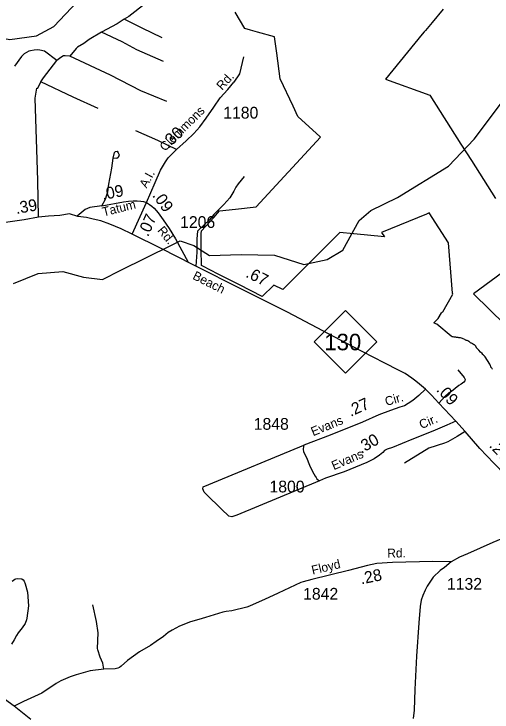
# Model space of a CAD drawing. Extents: x 2104537 to 2336408, y 34176 to 229611.
# Drawn here: x 2197655 to 2202724, y 77773 to 85176 of the extents above; entities that cross this region are included whole.
import ezdxf

# ---------------------------------------------------------------- set-up
doc = ezdxf.new("R2010")
doc.units = 0
for name, color, linetype in [('Exist Boundary Political City Limit New', 7, 'Continuous'), ('Exist Hydrographic Creek Single Shore', 7, 'Continuous'), ('Exist Road Non-System Type 51', 7, 'Continuous'), ('Exist Road Primary NC Attributed', 7, 'Continuous'), ('Exist Road Primary NC Label', 7, 'Continuous'), ('Exist Road Primary NC Mileage Hundredths English Label', 7, 'Continuous'), ('Exist Road Primary NC Shield CELL', 7, 'Continuous'), ('Exist Road Primary NC Shield Number Label', 7, 'Continuous'), ('Exist Road Secondary Mileage Hundredths English Label', 7, 'Continuous'), ('Exist Road Secondary Type 51 Attributed', 7, 'Continuous'), ('Exist Road Secondary Type 51 Label', 7, 'Continuous'), ('Exist Road Secondary Type 51 Number Label', 7, 'Continuous'), ('Map Preparation Boundary City Limit Buffer Line', 7, 'Continuous')]:
    doc.layers.add(name, color=color, linetype=linetype)

msp = doc.modelspace()

# ---------------------------------------------------------------- linework, layer by layer
at = {"layer": 'Exist Boundary Political City Limit New'}
for points in [[(2202204.2, 85228.7), (2202087.8, 85086.7)], [(2200288, 82179.3), (2200045.5, 82303.6), (2200004.8, 82324.6), (2199934.5, 82360), (2199821.2, 82417), (2199656.2, 82500), (2199643, 82506.9), (2199641, 82676.7), (2199639.2, 82845.5), (2199641.8, 82874.5), (2199772.5, 83017.8), (2199835.2, 83088.4), (2200004.8, 83106.6), (2200222, 83129.9), (2200905.8, 83869.1), (2200903.2, 83871.4), (2200666.5, 84087.6), (2200615.5, 84197), (2200479, 84489.6), (2200440.5, 84758.7), (2200416.2, 84933.5), (2200237.5, 84984.8), (2200163.8, 85005.9), (2200101.2, 85023.7), (2200000, 85193.9)], [(2202087.8, 85086.7), (2202016.8, 85000), (2202005.8, 84986.6), (2201984.8, 84961), (2201594, 84483.4), (2202064.2, 84314.4), (2202394, 83796.4), (2202504.8, 83623.1), (2202760.8, 83220)], [(2202714.5, 81427.8), (2202712.8, 81431.9), (2202710.5, 81435.9), (2202707.5, 81443.5), (2202706, 81447.4), (2202704.2, 81453), (2202703.8, 81454.5), (2202699.5, 81461.9), (2202649.8, 81538.7), (2202644.8, 81546.4), (2202642.8, 81549.4), (2202641.5, 81551), (2202638.5, 81553.9), (2202636.2, 81556.2), (2202634, 81558), (2202630.8, 81560.6), (2202628.2, 81562.5), (2202625.5, 81565.5), (2202617.5, 81574.4), (2202601.8, 81590.9), (2202582.2, 81611.7), (2202568.2, 81625.8), (2202565.8, 81627.9), (2202563.2, 81630.8), (2202561.2, 81633.2), (2202559.8, 81635.7), (2202558.2, 81638.6), (2202556.8, 81641.4), (2202554.8, 81646), (2202552.5, 81651), (2202550.8, 81654.3), (2202548.5, 81657.5), (2202546.5, 81659.6), (2202544.5, 81661.5), (2202542.8, 81662.9), (2202540.5, 81664.4), (2202538.2, 81665.8), (2202535.5, 81667.2), (2202533.8, 81668.2), (2202531.8, 81669.5), (2202530.5, 81670.3), (2202527.8, 81671.9), (2202522.2, 81675.3), (2202520.2, 81676.5), (2202517.8, 81677.9), (2202515.8, 81679.1), (2202514, 81680.1), (2202511.8, 81681.3), (2202504.8, 81684.6), (2202501, 81686.2), (2202496.2, 81689), (2202491, 81691.7), (2202483.5, 81697.6), (2202476.2, 81702.6), (2202467.5, 81708.3), (2202459, 81712.2), (2202449.2, 81714.3), (2202444.5, 81716.5), (2202439.5, 81719.3), (2202434, 81722.4), (2202417.8, 81729.9), (2202409.5, 81733.9), (2202401.2, 81737.8), (2202391.2, 81739.9), (2202382.2, 81741.1), (2202370.5, 81742.5), (2202364, 81744.4), (2202356.5, 81745.2), (2202348.2, 81746.4), (2202340, 81747.4), (2202330.5, 81748.3), (2202323.2, 81750.2), (2202313.5, 81750.9), (2202309.2, 81752), (2202302.8, 81753.8), (2202296.5, 81755.7), (2202292.2, 81757.9), (2202289.8, 81759.9), (2202137.5, 81886.4), (2202128, 81890.3), (2202105.5, 81901.6), (2202152.5, 81945.2), (2202186.8, 82006.2), (2202195, 82012), (2202202.8, 82017.7), (2202306.5, 82206.1), (2202306, 82213.7), (2202261.8, 82748.2), (2202056.5, 83066.1), (2202027.8, 83051.3), (2201550.5, 82857.1), (2201585, 82813.8), (2201258, 82845.5), (2201257.2, 82845.1), (2201253.5, 82845.5), (2201110.2, 82859.4), (2200752.8, 82500), (2200506.2, 82252.5), (2200411.8, 82301.5), (2200288, 82179.3)], [(2202902.2, 82482.8), (2202527.8, 82207.4), (2203532.2, 81224.5)], [(2202727.8, 81408.3), (2202723.8, 81412.6), (2202720, 81418.2), (2202716.5, 81424.3), (2202714.5, 81427.8)]]:
    msp.add_lwpolyline(points, dxfattribs=at)
at = {"layer": 'Exist Hydrographic Creek Single Shore'}
for points in [[(2197393.7, 84998.8), (2197476.7, 84931.5), (2197610.6, 84906), (2197893.6, 84943.1), (2198076.7, 85044.6), (2198448.7, 85437.7), (2198597.8, 85530), (2198946.8, 85631.5), (2199129.7, 85769), (2199418.8, 86084.9), (2199707.7, 86437), (2199831.8, 86638), (2200086.6, 87197.4), (2200225.7, 87450.6), (2200663.7, 88062.1), (2200770.7, 88220.8), (2200985.8, 88456.2)], [(2197651.5, 82316.3), (2197912.9, 82423.4), (2198174.3, 82444.9), (2198392.8, 82384.9), (2198594.2, 82359.1), (2198787, 82457.7), (2199326.8, 82723.6), (2199416.8, 82770.7), (2199562.5, 82719.3), (2199729.6, 82616.4), (2200063.8, 82624.9), (2200417.8, 82617.6), (2200726.8, 82519.7), (2200975.7, 82574), (2201141.8, 82672.5), (2201314.7, 82984.1), (2201438.8, 83093.2), (2201721.7, 83228.9), (2202260.8, 83562.9), (2202533.7, 83849.6), (2202962.7, 84418.8)]]:
    msp.add_lwpolyline(points, dxfattribs=at)
at = {"layer": 'Exist Road Non-System Type 51'}
for points in [[(2199254.6, 85469), (2199106.3, 85333.1), (2199051, 85288.2), (2198872.8, 85149.9), (2198823, 85121.4)], [(2198823, 85121.4), (2198749.6, 85072.3), (2198584.8, 84982.3)], [(2199227.6, 84922.6), (2199014.4, 85023.8), (2198823, 85121.4)], [(2198584.8, 84982.3), (2198453.7, 84904.4), (2198394.2, 84863.9), (2198327.5, 84823.5), (2198313.1, 84810.7), (2198245.9, 84730)], [(2199239.2, 84670.8), (2198957.2, 84796.9), (2198802.3, 84879), (2198584.8, 84982.3)], [(2198108.6, 84684.1), (2197979.2, 84780.4), (2197928.6, 84793.5), (2197901.1, 84795.4), (2197867.9, 84792.7), (2197829.1, 84786.2), (2197812.9, 84781), (2197761.5, 84753.8), (2197734, 84725.1), (2197661.2, 84622.2)], [(2198245.9, 84730), (2198199.1, 84732.5), (2198182, 84730.9), (2198152.1, 84714.7), (2198108.6, 84684.1)], [(2199274.6, 84247.2), (2199000.9, 84361.4), (2198678.7, 84527.4), (2198245.9, 84730)], [(2200087.8, 84722), (2200045.7, 84542), (2199987.3, 84451.2)], [(2197941.4, 84455.7), (2197969.2, 84498.1), (2198108.6, 84684.1)], [(2197916.4, 83019.9), (2197907.5, 83408.4), (2197881.5, 84281.6), (2197896.8, 84388.8), (2197906.4, 84390.7), (2197941.4, 84455.7)], [(2198549.2, 84173.6), (2198281.8, 84294.2), (2197941.4, 84455.7)], [(2199379.4, 83740.3), (2199182, 83834), (2198946.5, 83936.9)], [(2198706.3, 83647.6), (2198720.9, 83706.1), (2198732.6, 83717), (2198749.1, 83719.9), (2198761.5, 83704.3), (2198767.8, 83688.4), (2198769.3, 83682.2), (2198764.3, 83660.6), (2198758.3, 83652.5), (2198744.3, 83644.3), (2198706.3, 83647.6)], [(2198585, 83140.1), (2198624.1, 83210.6), (2198641.1, 83259.8), (2198648.9, 83290.8), (2198660, 83371), (2198691.8, 83539.6), (2198706.3, 83647.6)], [(2200094.9, 83453.3), (2200033.3, 83376.3), (2200006.9, 83341), (2199987.1, 83297), (2199945.3, 83226.6), (2199881.5, 83156.1), (2199822.1, 83098.9), (2199773.7, 83050.5), (2199729.7, 82993.3), (2199670.3, 82938.2), (2199602.1, 82872.2), (2199593.3, 82790.8), (2199595.5, 82649.9), (2199583.1, 82502.4)], [(2198585, 83140.1), (2198459.8, 83123.4), (2198409.8, 83102.2), (2198324.6, 83030.7)], [(2199369.5, 82790.1), (2199502, 82543.3)], [(2202362.7, 81402.9), (2202427.7, 81321.6), (2202438.1, 81299.7), (2202436.2, 81284), (2202424.4, 81269.8), (2202396.8, 81249.3), (2202372.9, 81237), (2202293.6, 81171.9), (2202265.8, 81157.7), (2202226.4, 81123), (2202161.3, 81050.1)], [(2202439.3, 80749.8), (2202355.9, 80694.7), (2202255.4, 80638.9), (2202219, 80622.8), (2202053.3, 80570.9), (2201794.6, 80411.3)], [(2200895, 80223.6), (2200018.2, 79860.9), (2199966, 79844.6), (2199934.5, 79849.4), (2199929.6, 79853.4), (2199857.4, 79920.4), (2199691.1, 80088.3), (2199672.3, 80105.8), (2199659.2, 80141.8), (2199662.5, 80161.4), (2199721.2, 80187.5), (2200728.9, 80603.7)], [(2200728.9, 80603.7), (2200723.6, 80588.1), (2200720.1, 80562.3), (2200725.1, 80534.2), (2200757.6, 80470.7), (2200788.5, 80391.9), (2200819.4, 80323.8), (2200847.3, 80274.3), (2200857.5, 80258.6), (2200866.9, 80244.5), (2200884.5, 80230.4), (2200895, 80223.6)], [(2197634.8, 79159.5), (2197665.1, 79183.5), (2197674.3, 79186), (2197695.4, 79189.2), (2197738.3, 79184.8), (2197752.8, 79173.6), (2197762.8, 79161), (2197773.4, 79133.2), (2197798.2, 79043.5), (2197808.2, 78897.6), (2197790, 78769.4), (2197786.3, 78751.4), (2197772.8, 78713.3), (2197743.1, 78667), (2197700, 78614.3), (2197682.8, 78586.4), (2197658.9, 78537.7), (2197629.5, 78493.6)], [(2200813.4, 79179.4), (2200722.4, 79154.3), (2200694.9, 79145.1), (2200455.4, 79032.9), (2200359.1, 78986.5), (2200318.1, 78970.9), (2200153, 78896.7), (2200122.9, 78885.5), (2199965.6, 78846.5), (2199903.8, 78839.5), (2199869.9, 78832.9), (2199686.4, 78776.8), (2199616.7, 78753.8), (2199525.1, 78728.7), (2199411.6, 78683), (2199334.1, 78642.1), (2199290.6, 78615.8), (2199240.9, 78575.1), (2199163.7, 78520.1), (2199102.3, 78479.3), (2198987.1, 78411.6), (2198858, 78319.6), (2198791.3, 78259.3), (2198773.3, 78247.1), (2198755.4, 78238.6), (2198727.4, 78230.3), (2198609.5, 78226.7)], [(2198609.5, 78226.7), (2198597.7, 78290.9), (2198569.7, 78356.4), (2198542.6, 78431.7), (2198540, 78447.2), (2198546.5, 78614), (2198530.7, 78733.8), (2198492.2, 78911.3)], [(2198609.5, 78226.7), (2198461.6, 78208.9), (2198315.1, 78169), (2198250.4, 78148), (2198150.8, 78103), (2198101.4, 78074.1), (2197950.1, 77974), (2197755.9, 77885.9), (2197656.5, 77836.6)]]:
    msp.add_lwpolyline(points, dxfattribs=at)
at = {"layer": 'Exist Road Primary NC Attributed'}
for points in [[(2198910, 82840.3), (2198792.8, 82897.7), (2198670.7, 82947.4), (2198575.2, 82981.8), (2198495.1, 83000.9), (2198424.4, 83016.1), (2198332.8, 83029.5), (2198244.2, 83056.3), (2198140, 83037.2), (2198021.7, 83031.4), (2197916.7, 83020), (2197764, 82993.2), (2197540.7, 82960.8), (2197359.3, 82930.2), (2197281.1, 82926.4), (2197164.3, 82918.8), (2197082.2, 82920.7), (2197015.4, 82928.3), (2196924.4, 82951.6)], [(2202017.5, 81197), (2201956.5, 81249.6), (2201917.2, 81281.6), (2201875.2, 81314.1), (2201804.5, 81361.8), (2201733.9, 81398.1), (2201588.9, 81472.6), (2201464.8, 81537.5), (2201246, 81650.6), (2200557, 82013.4), (2200089.3, 82248.3), (2199556.7, 82515.6), (2199217, 82687.5), (2198910, 82840.3)], [(2202339.4, 80858), (2202161.3, 81050.1), (2202082.3, 81135), (2202017.5, 81197)], [(2203300, 79807.4), (2203159.5, 79969.2), (2202997.4, 80139), (2202871.6, 80283.2), (2202741.9, 80413.9), (2202595.6, 80569.6), (2202439.3, 80749.8), (2202339.4, 80858)]]:
    msp.add_lwpolyline(points, dxfattribs=at)
at = {"layer": 'Exist Road Primary NC Shield CELL'}
msp.add_lwpolyline([(2200837, 81699.1), (2201170, 82032.1), (2201502.9, 81699.1), (2201170, 81366.1)], close=True, dxfattribs=at)
at = {"layer": 'Exist Road Secondary Type 51 Attributed'}
msp.add_line((2198910, 82840.3), (2199059.2, 83176.1), dxfattribs=at)
for points in [[(2199059.2, 83176.1), (2199151, 83387.9), (2199208.7, 83519.7), (2199260.2, 83608.3), (2199288.4, 83649.2), (2199329.8, 83687.7), (2199379.4, 83740.3), (2199480.2, 83831.8), (2199563, 83907.1), (2199624.8, 83979.3), (2199692.8, 84072), (2199773.1, 84187.4), (2199843.1, 84286.3), (2199921.4, 84374.9), (2199987.3, 84451.2)], [(2198585, 83140.1), (2198816.1, 83184.3), (2198868.3, 83191.2), (2198920.5, 83195.3), (2198961.7, 83195.3), (2199001.5, 83192.6), (2199027.6, 83187.1), (2199059.2, 83176.1)], [(2199059.2, 83176.1), (2199093.5, 83155.5), (2199118.2, 83137.6), (2199142.9, 83117), (2199182.8, 83068.9), (2199237.7, 82992), (2199300.9, 82900), (2199369.5, 82790.1)], [(2202017.5, 81197), (2201949.2, 81131.2), (2201883, 81078.5), (2201836.1, 81046.6), (2201794.4, 81021.9), (2201746, 81005.3), (2201646.8, 80972.2), (2201522, 80923.9), (2201350.3, 80846.2), (2201007.9, 80708.7), (2200728.9, 80603.7)], [(2202339.4, 80858), (2202243.8, 80816.4), (2202097.3, 80751), (2201873.5, 80663.8), (2201667.6, 80578.6), (2201612.1, 80560.8), (2201584.4, 80545), (2201564.6, 80525.1), (2201529, 80497.4), (2201475.5, 80457.8), (2201396.3, 80418.2), (2201156.7, 80321.1), (2200959.3, 80254.5), (2200895, 80223.6)], [(2203300, 79807.4), (2203190.6, 79761.9), (2202732.9, 79570.8), (2202463.6, 79451.9), (2202380.5, 79416.2), (2202291.8, 79366.1)], [(2202291.8, 79366.1), (2202095.4, 79368), (2201669.2, 79358.8), (2201500.9, 79346.9), (2201403.8, 79327.1), (2201201.9, 79275.6), (2200813.4, 79179.4)], [(2202291.8, 79366.1), (2202218.3, 79307.6), (2202174.6, 79275), (2202099.4, 79202), (2202034.6, 79109.1), (2202013.2, 79066.8), (2201990, 79007.9), (2201974.1, 78958.4), (2201962.2, 78891.1), (2201946.4, 78717.7), (2201924.6, 78367.1), (2201906.8, 78013.8), (2201898.9, 77793.9), (2201889, 77704.8)], [(2197834.2, 77695.2), (2197656.5, 77836.6), (2197357.8, 78052.1)]]:
    msp.add_lwpolyline(points, dxfattribs=at)
at = {"layer": 'Map Preparation Boundary City Limit Buffer Line'}
for points in [[(2202204.2, 85228.7), (2202087.8, 85086.7)], [(2200288, 82179.3), (2200045.5, 82303.6), (2200004.8, 82324.6), (2199934.5, 82360), (2199821.2, 82417), (2199656.2, 82500), (2199643, 82506.9), (2199641, 82676.7), (2199639.2, 82845.5), (2199641.8, 82874.5), (2199772.5, 83017.8), (2199835.2, 83088.4), (2200004.8, 83106.6), (2200222, 83129.9), (2200905.8, 83869.1), (2200903.2, 83871.4), (2200666.5, 84087.6), (2200615.5, 84197), (2200479, 84489.6), (2200440.5, 84758.7), (2200416.2, 84933.5), (2200237.5, 84984.8), (2200163.8, 85005.9), (2200101.2, 85023.7), (2200000, 85193.9)], [(2202087.8, 85086.7), (2202016.8, 85000), (2202005.8, 84986.6), (2201984.8, 84961), (2201594, 84483.4), (2202064.2, 84314.4), (2202394, 83796.4), (2202504.8, 83623.1), (2202760.8, 83220)], [(2202714.5, 81427.8), (2202712.8, 81431.9), (2202710.5, 81435.9), (2202707.5, 81443.5), (2202706, 81447.4), (2202704.2, 81453), (2202703.8, 81454.5), (2202699.5, 81461.9), (2202649.8, 81538.7), (2202644.8, 81546.4), (2202642.8, 81549.4), (2202641.5, 81551), (2202638.5, 81553.9), (2202636.2, 81556.2), (2202634, 81558), (2202630.8, 81560.6), (2202628.2, 81562.5), (2202625.5, 81565.5), (2202617.5, 81574.4), (2202601.8, 81590.9), (2202582.2, 81611.7), (2202568.2, 81625.8), (2202565.8, 81627.9), (2202563.2, 81630.8), (2202561.2, 81633.2), (2202559.8, 81635.7), (2202558.2, 81638.6), (2202556.8, 81641.4), (2202554.8, 81646), (2202552.5, 81651), (2202550.8, 81654.3), (2202548.5, 81657.5), (2202546.5, 81659.6), (2202544.5, 81661.5), (2202542.8, 81662.9), (2202540.5, 81664.4), (2202538.2, 81665.8), (2202535.5, 81667.2), (2202533.8, 81668.2), (2202531.8, 81669.5), (2202530.5, 81670.3), (2202527.8, 81671.9), (2202522.2, 81675.3), (2202520.2, 81676.5), (2202517.8, 81677.9), (2202515.8, 81679.1), (2202514, 81680.1), (2202511.8, 81681.3), (2202504.8, 81684.6), (2202501, 81686.2), (2202496.2, 81689), (2202491, 81691.7), (2202483.5, 81697.6), (2202476.2, 81702.6), (2202467.5, 81708.3), (2202459, 81712.2), (2202449.2, 81714.3), (2202444.5, 81716.5), (2202439.5, 81719.3), (2202434, 81722.4), (2202417.8, 81729.9), (2202409.5, 81733.9), (2202401.2, 81737.8), (2202391.2, 81739.9), (2202382.2, 81741.1), (2202370.5, 81742.5), (2202364, 81744.4), (2202356.5, 81745.2), (2202348.2, 81746.4), (2202340, 81747.4), (2202330.5, 81748.3), (2202323.2, 81750.2), (2202313.5, 81750.9), (2202309.2, 81752), (2202302.8, 81753.8), (2202296.5, 81755.7), (2202292.2, 81757.9), (2202289.8, 81759.9), (2202137.5, 81886.4), (2202128, 81890.3), (2202105.5, 81901.6), (2202152.5, 81945.2), (2202186.8, 82006.2), (2202195, 82012), (2202202.8, 82017.7), (2202306.5, 82206.1), (2202306, 82213.7), (2202261.8, 82748.2), (2202056.5, 83066.1), (2202027.8, 83051.3), (2201550.5, 82857.1), (2201585, 82813.8), (2201258, 82845.5), (2201257.2, 82845.1), (2201253.5, 82845.5), (2201110.2, 82859.4), (2200752.8, 82500), (2200506.2, 82252.5), (2200411.8, 82301.5), (2200288, 82179.3)], [(2202902.2, 82482.8), (2202527.8, 82207.4), (2203532.2, 81224.5)], [(2202727.8, 81408.3), (2202723.8, 81412.6), (2202720, 81418.2), (2202716.5, 81424.3), (2202714.5, 81427.8)]]:
    msp.add_lwpolyline(points, dxfattribs=at)

# ---------------------------------------------------------------- texts
at = {"layer": 'Exist Road Primary NC Label'}
msp.add_text('Beach', height=95, rotation=333.32461, dxfattribs=at).set_placement((2199541.2, 82369.1))
at = {"layer": 'Exist Road Primary NC Mileage Hundredths English Label'}
for s, rotation, p in [('.39', 9.93075, (2197680.9, 83054.1)), ('.67', 333.33116, (2200103.2, 82391.3)), ('.09', 312.82186, (2202126.6, 81183.9)), ('.27', 313.2103, (2202686.4, 80591.2))]:
    msp.add_text(s, height=125, rotation=rotation, dxfattribs=at).set_placement(p)
at = {"layer": 'Exist Road Primary NC Shield Number Label'}
msp.add_text('130', height=175, dxfattribs=at).set_placement((2200946.1, 81609.4))
at = {"layer": 'Exist Road Secondary Mileage Hundredths English Label'}
for s, rotation, p in [('.30', 42.28621, (2199291.1, 83744.6)), ('.09', 10.82859, (2198597.3, 83202.7)), ('.09', 305.52567, (2199117.1, 83250.3)), ('.07', 66.0471, (2199076.6, 82806.4)), ('.27', 24.32539, (2201224.3, 80902.8)), ('.30', 29.75603, (2201337, 80510.1)), ('.28', 11.53954, (2201337.6, 79126))]:
    msp.add_text(s, height=125, rotation=rotation, dxfattribs=at).set_placement(p)
at = {"layer": 'Exist Road Secondary Type 51 Label'}
for s, rotation, p in [('Rd.', 47.51224, (2199861.5, 84361.6)), ('Clemmons', 44.82331, (2199255.4, 83713.4)), ('A.I.', 61.59354, (2199061.8, 83322.6)), ('Tatum', 13.89989, (2198604.6, 83028.8)), ('Rd.', 309.70911, (2199169.9, 82876.8)), ('Cir.', 15.97706, (2201603.7, 81018.5)), ('Evans ', 22.41182, (2200827.2, 80697.5)), ('Cir.', 22.87631, (2201975.5, 80772.4)), ('Evans', 23.21443, (2201046.5, 80337.2)), ('Rd.', 0.75316, (2201613.2, 79410.9)), ('Floyd ', 13.49133, (2200822.1, 79229.1))]:
    msp.add_text(s, height=95, rotation=rotation, dxfattribs=at).set_placement(p)
at = {"layer": 'Exist Road Secondary Type 51 Number Label'}
for s, p in [('1180', (2199873.9, 84066.7)), ('1206', (2199416.6, 82906.8)), ('1848', (2200197.3, 80766.3)), ('1800', (2200364.4, 80101.8)), ('1132', (2202245.9, 79069.7)), ('1842', (2200721.1, 78964.5))]:
    msp.add_text(s, height=125, dxfattribs=at).set_placement(p)

doc.saveas('drawing.dxf')
